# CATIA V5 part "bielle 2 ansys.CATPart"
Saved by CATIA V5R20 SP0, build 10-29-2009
Part number: bielle 2 ansys
Bounding box of the stored display mesh (mm): x -122.161 to 77.839, y -52.44 to 47.56, z 0 to 10
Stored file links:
  C:\Users\Cédric\Documents\IFMA-2A\IAO\Projet IAO\ccascaro\bielle 2 ansys.CATPart
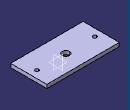
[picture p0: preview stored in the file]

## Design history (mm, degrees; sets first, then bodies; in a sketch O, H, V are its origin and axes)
Body1 (main body)
  Sketch1 on xy-plane, origin (0, 0, 0), H (1, 0, 0), V (0, 1, 0)
    line L1 (-122.1609, 47.5596) -> (77.8391, 47.5596)
    line L2 (77.8391, 47.5596) -> (77.8391, -52.4404)
    line L3 (77.8391, -52.4404) -> (-122.1609, -52.4404)
    line L4 (-122.1609, -52.4404) -> (-122.1609, 47.5596)
    circle A1 centre (57.8391, 0) radius 5
    point P5 (57.8391, 0)
    circle A2 centre (-102.1609, 0) radius 5
    point P6 (-102.1609, 0)
    circle A3 centre (-22.1609, 0) radius 10
    point P7 (-22.1609, 0)
    length L2 = 100
    length L1 = 200
    distance P5 L2 = 20
    distance P6 L4 = 20
    distance P7 L4 = 100
    horizontal: L1 H, L3 H
    vertical: L2 V, L4 V
    coincidence: P5 H, P6 H, P7 H
  Pad1: profile Sketch1, direction (0, 0, 1), length 10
